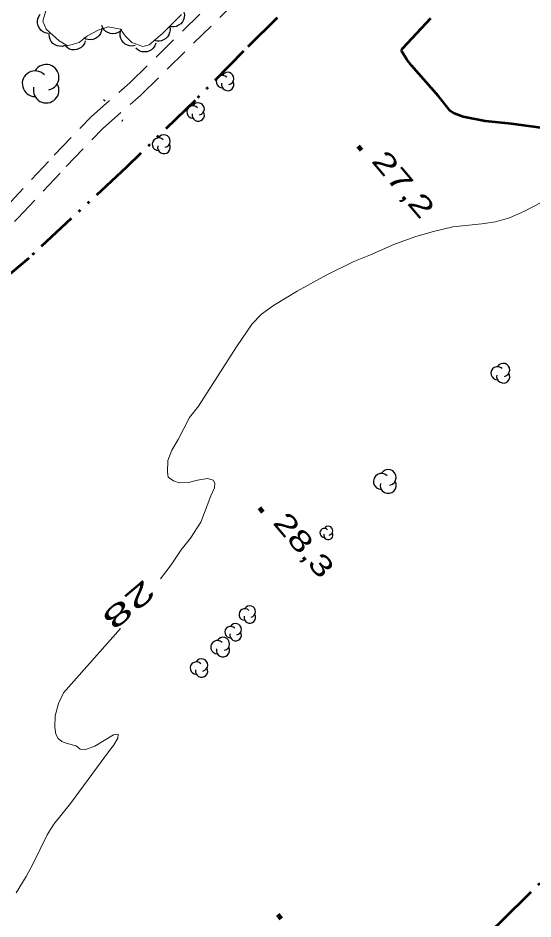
# Model space of a CAD drawing. Extents: x 386081 to 389416, y 5130568 to 5134082.
# Drawn here: x 388512.9 to 388588.2, y 5131918.7 to 5132050.5 of the extents above; entities that cross this region are included whole.
import ezdxf
from ezdxf.enums import TextEntityAlignment as Align

# ---------------------------------------------------------------- set-up
doc = ezdxf.new("R2010")
doc.units = 0
doc.header["$LTSCALE"] = 1.2
for name, pattern in [('DASH_DOUBLE_DOT', [9.2, 5, -1.2, 0.3, -1.2, 0.3, -1.2]), ('DOT_DASHED', [7.7, 5, -1.2, 0.3, -1.2]), ('MEDIUM_DASHED', [4.5, 3, -1.5])]:
    doc.linetypes.add(name, pattern=pattern)
for name, color, linetype, lineweight in [('19', 7, 'Continuous', 13), ('2', 7, 'Continuous', 13), ('26', 7, 'Continuous', 35), ('3', 7, 'Continuous', 140), ('4', 7, 'DASH_DOUBLE_DOT', 53), ('44', 7, 'Continuous', 25)]:
    doc.layers.add(name, color=color, linetype=linetype, lineweight=lineweight)

msp = doc.modelspace()

# ---------------------------------------------------------------- linework, layer by layer
at = {"layer": '19', "linetype": 'MEDIUM_DASHED'}
for points in [[(388441.51, 5131956.86), (388453.49, 5131967.84), (388477.1, 5131990.41), (388492.46, 5132004.74), (388502.71, 5132015.15), (388511.16, 5132022.92), (388518.17, 5132030.4), (388523.55, 5132036.01), (388529.2, 5132040.97), (388562.89, 5132074.01)], [(388443.16, 5131955.11), (388455.13, 5131966.09), (388478.75, 5131988.66), (388494.14, 5132003.01), (388504.38, 5132013.43), (388512.86, 5132021.21), (388519.92, 5132028.75), (388525.21, 5132034.26), (388530.83, 5132039.21), (388564.55, 5132072.28)]]:
    msp.add_lwpolyline(points, dxfattribs=at)
at = {"layer": '2'}
for points in [[(388533.69, 5131968.44), (388535.26, 5131970.5), (388536.71, 5131972.67), (388538.09, 5131974.41), (388539.6, 5131976.76), (388541.05, 5131980.61), (388541.6, 5131981.76), (388541.66, 5131982.42), (388541.42, 5131982.9), (388540.57, 5131983.14), (388539.13, 5131982.9), (388537.8, 5131982.53), (388536.42, 5131982.47), (388535.63, 5131982.77), (388534.85, 5131983.31), (388534.73, 5131984.03), (388534.79, 5131985.78), (388535.34, 5131987.28), (388536.3, 5131988.85), (388537.93, 5131992.04), (388539.26, 5131993.72), (388544.81, 5132002.39), (388547.1, 5132005.76), (388548.49, 5132007.15), (388550.24, 5132008.41), (388553.67, 5132010.52), (388558.01, 5132012.93), (388561.99, 5132014.86), (388564.4, 5132015.82), (388567.83, 5132017.33), (388570.9, 5132018.47), (388573.43, 5132019.2), (388576.45, 5132019.92), (388580.72, 5132020.35), (388582.71, 5132020.65), (388584.75, 5132021.25), (388586.92, 5132022.21), (388595.47, 5132026.67)], [(388512.61, 5131922.52), (388514.06, 5131924.93), (388515.08, 5131926.8), (388517.14, 5131931.01), (388518.1, 5131932.58), (388520.52, 5131935.59), (388526.25, 5131943.36), (388526.85, 5131944.08), (388527.46, 5131945.17), (388527.52, 5131945.71), (388526.85, 5131945.65), (388524.08, 5131943.96), (388522.75, 5131943.47), (388521.97, 5131943.53), (388521.37, 5131944.01), (388520.04, 5131944.37), (388519.26, 5131944.67), (388518.72, 5131945.09), (388518.42, 5131945.75), (388518.24, 5131946.78), (388518.3, 5131948.4), (388518.78, 5131950.21), (388519.51, 5131951.77), (388527.86, 5131961.18)]]:
    msp.add_lwpolyline(points, dxfattribs=at)
at = {"layer": '26'}
for p, q in [((388525.4, 5132038.48), (388525.47, 5132038.55)), ((388525.56, 5132038.34), (388525.4, 5132038.48)), ((388525.56, 5132038.34), (388525.62, 5132038.42)), ((388528.05, 5132035.38), (388527.98, 5132035.45)), ((388528.05, 5132035.38), (388527.98, 5132035.45)), ((388528.19, 5132035.52), (388528.05, 5132035.38)), ((388528.19, 5132035.52), (388528.05, 5132035.38)), ((388528.19, 5132035.52), (388528.13, 5132035.59)), ((388528.19, 5132035.52), (388528.13, 5132035.59))]:
    msp.add_line(p, q, dxfattribs=at)
at = {"layer": '3'}
for p, q in [((388562.61, 5132031.73), (388563.12, 5132031.12)), ((388548.18, 5131978.83), (388548.69, 5131978.22)), ((388550.86, 5131919.35), (388551.37, 5131918.74))]:
    msp.add_line(p, q, dxfattribs=at)
at = {"layer": '4'}
for points in [[(388403.08, 5131676.15), (388398.8, 5131683.5), (388385.24, 5131705.68), (388376.19, 5131718.23), (388378.12, 5131720.75), (388380.58, 5131723.47), (388405.01, 5131746.47), (388448.58, 5131788.82), (388515.07, 5131852.58), (388524.6, 5131861.96), (388550.41, 5131886.49), (388583.66, 5131918.46), (388613.94, 5131948.36), (388649.63, 5131983.32), (388677.59, 5132010.13), (388707.98, 5132038.7), (388732.5, 5132062.17)], [(388550.76, 5132050.49), (388545.85, 5132045.63), (388538.76, 5132038.43), (388528.74, 5132028.67), (388514.45, 5132015.36), (388507.53, 5132009.59), (388503.89, 5132006.34), (388495.93, 5131998.76), (388493.82, 5131996.84), (388488.46, 5131991.71), (388475.39, 5131978.94), (388472.36, 5131975.88), (388469.33, 5131973.01), (388458.14, 5131961.88), (388456.19, 5131960.05), (388455.5, 5131959.26), (388441.98, 5131946.49), (388418.93, 5131924.94), (388400.96, 5131907.59), (388382.99, 5131889.58)], [(388614.65, 5132031.54), (388611.46, 5132032.49), (388609.26, 5132032.97), (388607.28, 5132033.17), (388605.12, 5132033.17), (388600.2, 5132033.47), (388598.06, 5132033.7), (388595.57, 5132033.8), (388590.44, 5132034.25), (388585.05, 5132034.98), (388581.2, 5132035.37), (388577.98, 5132036), (388576.57, 5132036.54), (388576.05, 5132036.9), (388574.36, 5132039.05), (388570.4, 5132043.54), (388569.74, 5132044.38), (388569, 5132045.59), (388568.97, 5132045.79), (388569.14, 5132046.08), (388573.33, 5132050.51)]]:
    msp.add_lwpolyline(points, dxfattribs=at)
at = {"layer": '44', "linetype": 'DOT_DASHED', "lineweight": 13}
msp.add_lwpolyline([(388536.77, 5132051), (388533.99, 5132048.23), (388532.06, 5132046.54), (388531.1, 5132046.3), (388529.53, 5132046.9), (388528.56, 5132047.87), (388527.84, 5132048.83), (388526.03, 5132049.19), (388524.58, 5132048.71), (388523.02, 5132047.86), (388521.81, 5132046.9), (388520.12, 5132046.42), (388518.91, 5132047.14), (388516.99, 5132048.82), (388516.5, 5132050.03), (388516.99, 5132051.71)], dxfattribs=at)
at = {"layer": '44'}
for points in [[(388517.23, 5132048.23), (388516.82, 5132048.32), (388516.46, 5132048.51), (388516.2, 5132048.71), (388515.99, 5132048.99), (388515.82, 5132049.32), (388515.74, 5132049.7), (388515.7, 5132050.02), (388515.77, 5132050.36), (388515.9, 5132050.71), (388516.1, 5132051.01)], [(388537.12, 5132051.35), (388537.2, 5132050.94), (388537.16, 5132050.53), (388537.08, 5132050.21), (388536.9, 5132049.91), (388536.66, 5132049.63), (388536.35, 5132049.41), (388536.06, 5132049.25), (388535.72, 5132049.18), (388535.35, 5132049.16), (388535, 5132049.23)], [(388525.11, 5132049), (388525.07, 5132048.58), (388524.91, 5132048.21), (388524.75, 5132047.92), (388524.49, 5132047.68), (388524.18, 5132047.47), (388523.82, 5132047.35), (388523.5, 5132047.28), (388523.15, 5132047.31), (388522.79, 5132047.4), (388522.47, 5132047.56)], [(388528.06, 5132048.79), (388527.77, 5132048.49), (388527.41, 5132048.3), (388527.1, 5132048.19), (388526.74, 5132048.17), (388526.38, 5132048.21), (388526.02, 5132048.34), (388525.73, 5132048.49), (388525.48, 5132048.74), (388525.26, 5132049.04), (388525.12, 5132049.37)], [(388535.06, 5132049.17), (388535.11, 5132048.75), (388535.04, 5132048.35), (388534.94, 5132048.03), (388534.75, 5132047.74), (388534.49, 5132047.48), (388534.16, 5132047.28), (388533.87, 5132047.13), (388533.52, 5132047.09), (388533.15, 5132047.1), (388532.8, 5132047.19)], [(388519.73, 5132046.43), (388519.32, 5132046.32), (388518.92, 5132046.33), (388518.59, 5132046.39), (388518.28, 5132046.55), (388517.98, 5132046.76), (388517.74, 5132047.06), (388517.56, 5132047.34), (388517.46, 5132047.67), (388517.43, 5132048.04), (388517.47, 5132048.4)], [(388529.99, 5132046.44), (388529.58, 5132046.36), (388529.18, 5132046.4), (388528.86, 5132046.48), (388528.55, 5132046.65), (388528.27, 5132046.89), (388528.05, 5132047.2), (388527.89, 5132047.49), (388527.82, 5132047.83), (388527.8, 5132048.2), (388527.87, 5132048.56)], [(388522.7, 5132047.15), (388522.57, 5132046.75), (388522.33, 5132046.42), (388522.11, 5132046.18), (388521.8, 5132046), (388521.46, 5132045.87), (388521.08, 5132045.83), (388520.75, 5132045.83), (388520.42, 5132045.93), (388520.09, 5132046.1), (388519.81, 5132046.33)], [(388533.02, 5132046.78), (388532.87, 5132046.39), (388532.63, 5132046.06), (388532.4, 5132045.83), (388532.09, 5132045.66), (388531.74, 5132045.54), (388531.36, 5132045.51), (388531.03, 5132045.52), (388530.7, 5132045.63), (388530.37, 5132045.81), (388530.1, 5132046.05)]]:
    msp.add_lwpolyline(points, dxfattribs=at)
for centre, radius, start, end in [((388516.984, 5132041.801), 1.877, 282.26917, 149.72626), ((388515.37, 5132040.863), 1.877, 44.11537, 269.80396), ((388543.525, 5132041.63), 0.899, 282.26917, 149.72626), ((388542.752, 5132041.18), 0.899, 44.11537, 269.80396), ((388543.525, 5132040.731), 0.899, 166.93686, 29.62122), ((388516.984, 5132039.924), 1.877, 166.93686, 29.62122), ((388538.452, 5132036.72), 0.899, 44.11537, 269.80396), ((388539.225, 5132037.17), 0.899, 282.26917, 149.72626), ((388539.225, 5132036.271), 0.899, 166.93686, 29.62122), ((388534.206, 5132032.473), 0.923, 282.26917, 149.72626), ((388533.412, 5132032.011), 0.923, 44.11537, 269.80396), ((388534.206, 5132031.549), 0.923, 166.93686, 29.62122), ((388582.994, 5131998.522), 0.962, 44.11537, 269.80396), ((388582.994, 5131998.522), 0.962, 44.11537, 269.80396), ((388583.822, 5131999.003), 0.962, 282.26917, 149.72626), ((388583.822, 5131999.003), 0.962, 282.26917, 149.72626), ((388583.822, 5131998.041), 0.962, 166.93686, 29.62122), ((388583.822, 5131998.041), 0.962, 166.93686, 29.62122), ((388567.007, 5131983.28), 1.166, 282.26917, 149.72626), ((388567.007, 5131983.28), 1.166, 282.26917, 149.72626), ((388566.004, 5131982.696), 1.166, 44.11537, 269.80396), ((388566.004, 5131982.696), 1.166, 44.11537, 269.80396), ((388567.007, 5131982.113), 1.166, 166.93686, 29.62122), ((388567.007, 5131982.113), 1.166, 166.93686, 29.62122), ((388557.679, 5131975.165), 0.659, 44.11537, 269.80396), ((388557.679, 5131975.165), 0.659, 44.11537, 269.80396), ((388558.245, 5131974.835), 0.659, 166.93686, 29.62122), ((388558.245, 5131974.835), 0.659, 166.93686, 29.62122), ((388558.245, 5131975.494), 0.659, 282.26917, 149.72626), ((388558.245, 5131975.494), 0.659, 282.26917, 149.72626), ((388546.035, 5131963.239), 0.847, 44.11537, 269.80396), ((388546.035, 5131963.239), 0.847, 44.11537, 269.80396), ((388546.764, 5131963.663), 0.847, 282.26917, 149.72626), ((388546.764, 5131963.663), 0.847, 282.26917, 149.72626), ((388546.764, 5131962.816), 0.847, 166.93686, 29.62122), ((388546.764, 5131962.816), 0.847, 166.93686, 29.62122), ((388543.965, 5131960.649), 0.847, 44.11537, 269.80396), ((388543.965, 5131960.649), 0.847, 44.11537, 269.80396), ((388544.694, 5131960.226), 0.847, 166.93686, 29.62122), ((388544.694, 5131960.226), 0.847, 166.93686, 29.62122), ((388544.694, 5131961.073), 0.847, 282.26917, 149.72626), ((388544.694, 5131961.073), 0.847, 282.26917, 149.72626), ((388542.014, 5131958.462), 0.962, 44.11537, 269.80396), ((388542.014, 5131958.462), 0.962, 44.11537, 269.80396), ((388542.842, 5131958.943), 0.962, 282.26917, 149.72626), ((388542.842, 5131958.943), 0.962, 282.26917, 149.72626), ((388542.842, 5131957.981), 0.962, 166.93686, 29.62122), ((388542.842, 5131957.981), 0.962, 166.93686, 29.62122), ((388539.716, 5131955.85), 0.9, 282.26917, 149.72626), ((388539.716, 5131955.85), 0.9, 282.26917, 149.72626), ((388538.942, 5131955.4), 0.9, 44.11537, 269.80396), ((388538.942, 5131955.4), 0.9, 44.11537, 269.80396), ((388539.716, 5131954.951), 0.9, 166.93686, 29.62122), ((388539.716, 5131954.951), 0.9, 166.93686, 29.62122)]:
    msp.add_arc(centre, radius, start, end, dxfattribs=at)

# ---------------------------------------------------------------- texts
at = {"layer": '2', "width": 1.9}
msp.add_text('28', height=3, rotation=220.275, dxfattribs=at).set_placement((388528.13, 5131965.769), align=Align.CENTER)
at = {"layer": '3'}
for s, width, p in [('27,2   ', 1.45, (388564.44, 5132029.51)), ('28,3   ', 1.4, (388550.01, 5131976.61))]:
    msp.add_text(s, height=3, rotation=310.294, dxfattribs=dict(at, width=width)).set_placement(p)

doc.saveas('drawing.dxf')
